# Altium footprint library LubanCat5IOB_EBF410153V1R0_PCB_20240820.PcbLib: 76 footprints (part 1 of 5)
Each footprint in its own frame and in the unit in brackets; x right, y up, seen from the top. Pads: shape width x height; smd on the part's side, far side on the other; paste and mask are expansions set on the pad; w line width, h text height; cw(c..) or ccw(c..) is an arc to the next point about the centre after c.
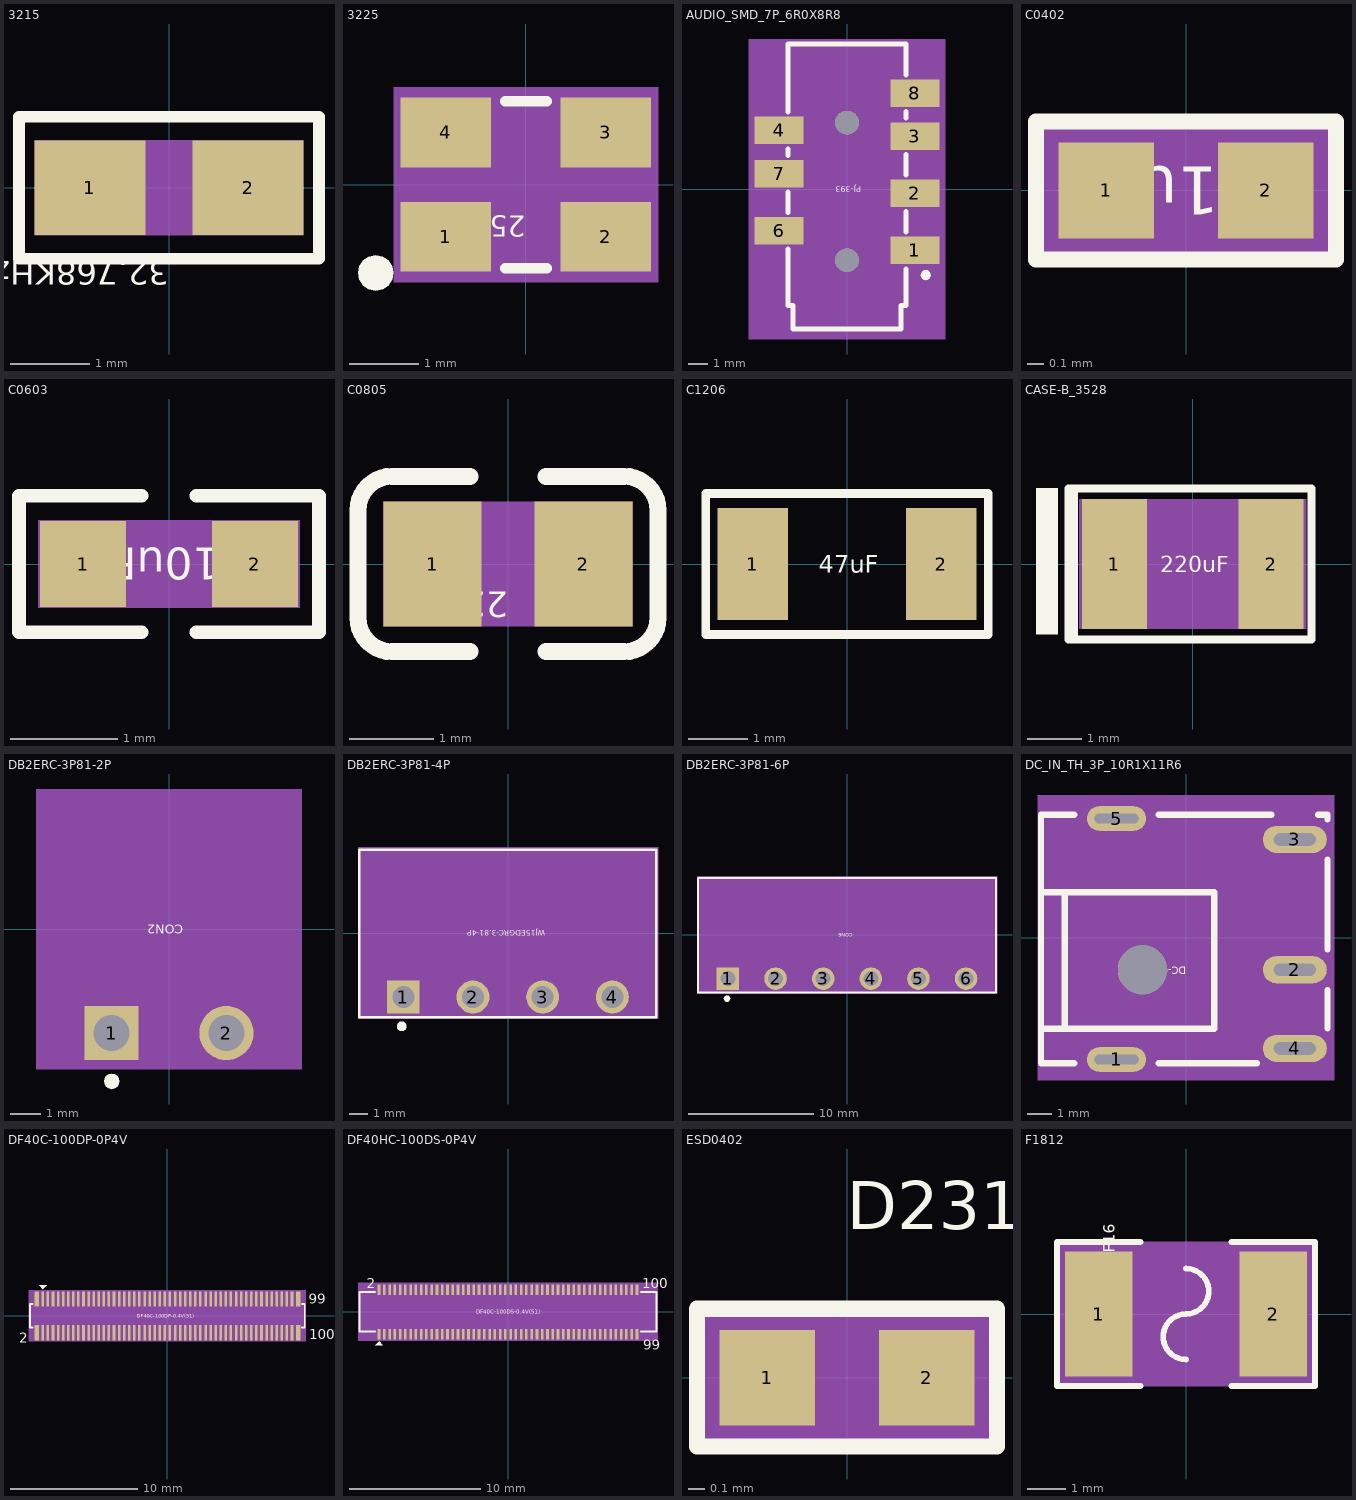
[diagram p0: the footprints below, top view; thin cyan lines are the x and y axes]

## 3215 [mm] "3215"
pads (2):
  rect 1.4x1.2 smd: 1(-1.001,0) 2(1.001,0)
Top Overlay:
  lines w0.15: -1.9,-0.899 1.9,-0.899 1.9,0.899 -1.9,0.899 -1.9,-0.899
  text "32.768KHz" at 0,-0.93 h0.3
Top 3D Body:
  region: -1.699,-0.599 1.699,-0.599 1.699,0.599 -1.699,0.599
Mechanical 15:
  text "1" at -1.001,-0.152 h0.38
  text "2" at 1.001,-0.152 h0.38
3D body: height 3.81, standoff 0, extent -1.699,-0.599 1.699,0.599

## 3225 [mm] "3225"
pads (4):
  rect 1.3x1 smd: 1(-1.15,-0.75) 2(1.15,-0.75) 3(1.15,0.75) 4(-1.15,0.75)
Top Overlay:
  dashed: -2.159,-1.015 -2.257,-1.035 -2.339,-1.09 -2.394,-1.172 -2.414,-1.27 -2.394,-1.368 -2.376,-1.395 -2.339,-1.45 -2.257,-1.505 -2.159,-1.525 -2.061,-1.505 -1.979,-1.45 -1.942,-1.395 -1.924,-1.368 -1.904,-1.27 -1.924,-1.172 -1.979,-1.09 -2.061,-1.035
  lines w0.15: -0.3,-1.2 0.3,-1.2 ; -0.3,1.2 0.3,1.2
  text "25MHz" at 0,-0.45 h0.3
Top 3D Body:
  region: -1.9,1.4 -1.9,-1.4 1.9,-1.4 1.9,1.4
Mechanical 15:
  text "3" at 1.15,0.394 h0.89
  text "2" at 1.15,-1.106 h0.89
  text "4" at -1.15,0.394 h0.89
  text "1" at -1.15,-1.106 h0.89
Top Assembly:
  lines w0.15: -1.6,-1.25 1.6,-1.25 1.6,1.25 -1.6,1.25 -1.6,-1.25
3D body: height 3.81, standoff 0, extent -1.9,-1.4 1.9,1.4

## AUDIO_SMD_7P_6R0X8R8 [mm] "AUDIO_SMD_7P_6R0X8R8"
pads (9):
  rect 2.5x1.4 smd: 1(3.45,-3.125) 2(3.45,-0.225) 3(3.45,2.675) 4(-3.45,2.975) 6(-3.45,-2.125) 7(-3.45,0.775) 8(3.45,4.875)
  round 1.2 hole 1.2 unplated: ""(0,-3.625) ""(0,3.375)
Top Overlay:
  dashed: 3.745,-4.375 3.765,-4.473 3.82,-4.555 3.902,-4.61 4,-4.63 4.098,-4.61 4.125,-4.592 4.18,-4.555 4.235,-4.473 4.255,-4.375 4.235,-4.277 4.18,-4.195 4.125,-4.158 4.098,-4.14 4,-4.12 3.902,-4.14 3.82,-4.195 3.765,-4.277
  lines w0.254: -3,-3.056 -3,-5.025 -3,-4.975 -3,-5.925 -2.75,-5.925 -2.75,-7.125 2.75,-7.125 2.75,-5.925 3,-5.925 3,-4.056 ; -3,-1.194 -3,-0.156 ; -3,1.706 -3,2.044 ; -3,3.906 -3,7.375 3,7.375 3,5.806 ; 3,-2.194 3,-1.156 ; 3,0.706 3,1.744 ; 3,3.606 3,3.944
  text "PJ-393" at 0.72,0.15 h0.3
Top 3D Body:
  region: -5,7.625 -5,-7.625 5,-7.625 5,7.625
Mechanical 15:
  text "6" at -3.196,-2.125 h0.64
  text "4" at -3.196,2.975 h0.64
  text "3" at 3.704,2.675 h0.64
  text "2" at 3.704,-0.225 h0.64
  text "1" at 3.704,-3.125 h0.64
  text "8" at 3.704,4.875 h0.64
  text "7" at -3.196,0.775 h0.64
3D body: height 3.81, standoff 0, extent -5,-7.625 5,7.625

## C0402 [mm] "C0402"
pads (2):
  rect 0.599x0.599 smd: 1(-0.5,0) 2(0.5,0)
Top Overlay:
  lines w0.102: -0.94,-0.432 0.94,-0.432 0.94,0.432 -0.94,0.432 -0.94,-0.432
  text "0.1uF" at 0.6,0.15 h0.3
Top 3D Body:
  region: 0.94,0.432 0.94,-0.432 -0.94,-0.432 -0.94,0.432
Mechanical 15:
  text "2" at 0.754,0 h0.64
  text "1" at -0.246,0 h0.64
Top Assembly:
  dashed: -0.94,-0.432 -0.94,0.432 0.94,0.432 0.94,-0.432
3D body: height 3.81, standoff 0, extent -0.94,-0.432 0.94,0.432

## C0603 [mil] "C0603"
pads (2):
  rect 31.5x31.5 smd: 1(-31.5,0) 2(31.5,0)
Top Overlay:
  lines w5: -10,-25 -55,-25 -55,25 -10,25 ; 10,-25 55,-25 55,25 10,25
  text "10uF" at 18.9,5.91 h11.81
Top 3D Body:
  region: -48,16 48,16 48,-16 -48,-16
Mechanical 15:
  text "1" at -13.5,0 h45
  text "2" at 49.5,0 h45
Top Assembly:
  text "C0603" at -117,37 h35
3D body: height 150, standoff 0, extent -48,-16 48,16

## C0805 [mm] "C0805"
pads (2):
  rect 1.16x1.47 smd: 1(-0.89,0) 2(0.89,0)
Top Overlay:
  lines w0.2: -0.45,-1.035 -1.37,-1.035 cw(c-1.37,-0.635) -1.77,-0.635 -1.77,0.635 cw(c-1.37,0.635) -1.37,1.035 -0.45,1.035 ; 0.45,-1.035 1.37,-1.035 ccw(c1.37,-0.635) 1.77,-0.635 1.77,0.635 ccw(c1.37,0.635) 1.37,1.035 0.45,1.035
  text "22uF" at 0,-0.33 h0.3
Top 3D Body:
  region: -1.47,-0.735 1.47,-0.735 1.47,0.735 -1.47,0.735
Mechanical 15:
  text "1" at -0.89,-0.315 h0.79
  text "2" at 0.89,-0.315 h0.79
3D body: height 3.81, standoff 0, extent -1.47,-0.735 1.47,0.735

## C1206 [mm] "C1206"
pads (2):
  rect 1.2x1.9 smd: 1(-1.6,0) 2(1.6,0)
Top Overlay:
  lines w0.15: -2.4,-1.2 -2.4,1.2 2.4,1.2 2.4,-1.2 0.6,-1.2 -2.4,-1.2
  text "47uF" at -0.48,-0.15 h0.3
Top 3D Body:
  lines w0.025: -2.4,-1.2 2.4,-1.2 2.4,1.2 -2.4,1.2 -2.4,-1.2
Mechanical 15:
  text "2" at 1.498,0 h0.25
  text "1" at -1.702,0 h0.25
Top Assembly:
  lines w0.025: -2.4,-1.2 2.4,-1.2 2.4,1.2 -2.4,1.2 -2.4,-1.2

## CASE-B_3528 [mm] "CASE-B_3528"
pads (2):
  rect 1.2x2.4 smd: 1(-1.45,0) 2(1.45,0)
Top Overlay:
  dashed: -2.9,1.4 -2.9,-1.3 -2.5,-1.3 -2.5,1.4
  lines w0.15: -2.2,1.4 -2.2,-1.4 2.2,-1.4 2.2,1.4 -2.3,1.4 -2.3,-1.4 -2.1,-1.4
  text "220uF" at -0.6,-0.15 h0.3
Top 3D Body:
  region: -2.1,1.2 -2.1,-1.2 2.1,-1.2 2.1,1.2
Mechanical 15:
  text "2" at 1.196,0 h0.64
  text "1" at -1.704,0 h0.64
Top Assembly:
  lines w0.15: -1.72,-1.1 1.78,-1.1 1.78,1.1 -1.72,1.1 -1.72,-1.1
3D body: height 3.81, standoff 0, extent -2.1,-1.2 2.1,1.2

## DB2ERC-3P81-2P [mm] "DB2ERC-3P81-2P"
pads (2):
  rect 1.8x1.8 / inner round 1.524 / far side rect 1.8x1.8 hole 1.2: 1(-1.905,-3.45)
  round 1.8 / inner round 1.524 / far side round 1.8 hole 1.2: 2(1.905,-3.45)
Top Overlay:
  dashed: -2.155,-5.05 -2.135,-5.148 -2.08,-5.23 -1.998,-5.285 -1.9,-5.305 -1.802,-5.285 -1.775,-5.267 -1.72,-5.23 -1.665,-5.148 -1.645,-5.05 -1.665,-4.952 -1.72,-4.87 -1.775,-4.833 -1.802,-4.815 -1.9,-4.795 -1.998,-4.815 -2.08,-4.87 -2.135,-4.952
  text "CON2" at 0.48,0.15 h0.3
Top 3D Body:
  region: -4.4,4.65 -4.4,-4.65 4.4,-4.65 4.4,4.65
Mechanical 15:
  text "2" at 2.159,-3.45 h0.64
  text "1" at -1.651,-3.45 h0.64
3D body: height 3.81, standoff 0, extent -4.4,-4.65 4.4,4.65

## DB2ERC-3P81-4P [mm] "DB2ERC-3P81-4P"
pads (4):
  rect 1.8x1.8 / inner round 1.524 / far side rect 1.8x1.8 hole 1.2: 1(-5.725,-3.5)
  round 1.8 / inner round 1.524 / far side round 1.8 hole 1.2: 2(-1.915,-3.5) 3(1.895,-3.5) 4(5.705,-3.5)
Top Overlay:
  dashed: -6.065,-5.1 -6.046,-5.198 -5.99,-5.28 -5.908,-5.335 -5.81,-5.355 -5.712,-5.335 -5.685,-5.317 -5.63,-5.28 -5.574,-5.198 -5.555,-5.1 -5.574,-5.002 -5.63,-4.92 -5.685,-4.883 -5.712,-4.864 -5.81,-4.845 -5.908,-4.864 -5.99,-4.92 -6.046,-5.002
  lines w0.15: -8.13,-4.6 8.11,-4.6 8.11,4.55 -8.13,4.55 -8.13,-4.6
  text "WJ15EDGRC-3.81-4P" at 2.04,0.15 h0.3
Top 3D Body:
  region: -8.2,4.7 -8.2,-4.7 8.2,-4.7 8.2,4.7
Mechanical 15:
  text "4" at 5.959,-3.5 h0.64
  text "3" at 2.149,-3.5 h0.64
  text "1" at -5.471,-3.5 h0.64
  text "2" at -1.661,-3.5 h0.64
3D body: height 3.81, standoff 0, extent -8.2,-4.7 8.2,4.7

## DB2ERC-3P81-6P [mm] "DB2ERC-3P81-6P"
pads (6):
  rect 1.8x1.8 / inner round 1.524 / far side rect 1.8x1.8 hole 1.2: 1(-9.525,-3.5)
  round 1.8 hole 1.2: 2(-5.715,-3.5) 5(5.715,-3.5)
  round 1.8 / inner round 1.524 / far side round 1.8 hole 1.2: 3(-1.905,-3.5) 4(1.905,-3.5) 6(9.525,-3.5)
Top Overlay:
  dashed: -9.855,-5.1 -9.836,-5.198 -9.78,-5.28 -9.698,-5.335 -9.6,-5.355 -9.502,-5.335 -9.475,-5.317 -9.42,-5.28 -9.364,-5.198 -9.345,-5.1 -9.364,-5.002 -9.42,-4.92 -9.475,-4.883 -9.502,-4.864 -9.6,-4.845 -9.698,-4.864 -9.78,-4.92 -9.836,-5.002
  lines w0.15: -11.93,-4.6 11.93,-4.6 11.93,4.55 -11.93,4.55 -11.93,-4.6
  text "CON6" at 0.48,0.15 h0.3
Top 3D Body:
  region: -12,4.7 -12,-4.7 12,-4.7 12,4.7
Mechanical 15:
  text "5" at 5.969,-3.5 h0.64
  text "2" at -5.461,-3.5 h0.64
  text "6" at 9.779,-3.5 h0.64
  text "4" at 2.159,-3.5 h0.64
  text "1" at -9.271,-3.5 h0.64
  text "3" at -1.651,-3.5 h0.64
3D body: height 3.81, standoff 0, extent -12,-4.7 12,4.7

## DC_IN_TH_3P_10R1X11R6 [mil] "DC_IN_TH_3P_10R1X11R6"
pads (6):
  oval 94.5x39.4 / inner round 60 / far side oval 94.5x39.4 hole 70.9 slot 15.7 at 90 deg: 1(-111.25,-194.9) 5(-111.25,190.9)
  oval 102.4x43.3 hole 66.9 slot 19.7 at 90 deg: 2(174.25,-51.2) 3(174.25,157.4)
  oval 102.4x43.3 / inner round 60 / far side oval 102.4x43.3 hole 66.9 slot 19.7 at 90 deg: 4(174.25,-177.2)
  round 78.7 hole 78.7 unplated: ""(-69.85,-51.2)
Top Overlay:
  lines w10: -232.25,-145.7 45.25,-145.7 45.25,72.8 -222.45,72.8 -232.25,72.8 ; -193.95,-145.7 -193.95,72.8 ; -178.95,-200.8 -232.25,-200.8 -232.25,196.8 -178.95,196.8 ; -43.45,-200.8 113.65,-200.8 ; -43.45,196.8 136.95,196.8 ; 211.45,196.8 226.35,196.8 226.35,189.7 ; 226.35,-145 226.35,-83.5 ; 226.35,-19 226.35,125.2
  text "DC-044A-20A" at 0.01,-46.06 h11.81
Top 3D Body:
  region: -237.25,-228.4 237.25,-228.4 237.25,228.4 -237.25,228.4
Mechanical 15:
  text "4" at 174.25,-187.2 h25
  text "2" at 174.25,-61.2 h25
  text "3" at 174.25,147.4 h25
  text "5" at -111.25,180.9 h25
  text "1" at -111.25,-204.9 h25
Mechanical 23:
  dashed: -232.25,-141.8 41.35,-141.8 41.35,68.9 -232.25,68.9 -232.25,78.7 51.15,78.7 51.15,-151.6 -232.25,-151.6
3D body: height 150, standoff 0, extent -237.25,-228.4 237.25,228.4

## DF40C-100DP-0P4V [mm] "DF40C-100DP-0P4V"
pads (104):
  rect 0.2x1.2 smd: 1(-9.8,1.325) 2(-9.8,-1.325) 3(-9.4,1.325) 4(-9.4,-1.325) 5(-9,1.325) 6(-9,-1.325) 7(-8.6,1.325) 8(-8.6,-1.325) 9(-8.2,1.325) 10(-8.2,-1.325) 11(-7.8,1.325) 12(-7.8,-1.325) 13(-7.4,1.325) 14(-7.4,-1.325) 15(-7,1.325) 16(-7,-1.325) 17(-6.6,1.325) 18(-6.6,-1.325) 19(-6.2,1.325) 20(-6.2,-1.325) 21(-5.8,1.325) 22(-5.8,-1.325) 23(-5.4,1.325) 24(-5.4,-1.325) 25(-5,1.325) 26(-5,-1.325) 27(-4.6,1.325) 28(-4.6,-1.325) 29(-4.2,1.325) 30(-4.2,-1.325) 31(-3.8,1.325) 32(-3.8,-1.325) 33(-3.4,1.325) 34(-3.4,-1.325) 35(-3,1.325) 36(-3,-1.325) 37(-2.6,1.325) 38(-2.6,-1.325) 39(-2.2,1.325) 40(-2.2,-1.325) 41(-1.8,1.325) 42(-1.8,-1.325) 43(-1.4,1.325) 44(-1.4,-1.325) 45(-1,1.325) 46(-1,-1.325) 47(-0.6,1.325) 48(-0.6,-1.325) 49(-0.2,1.325) 50(-0.2,-1.325) 51(0.2,1.325) 52(0.2,-1.325) 53(0.6,1.325) 54(0.6,-1.325) 55(1,1.325) 56(1,-1.325) 57(1.4,1.325) 58(1.4,-1.325) 59(1.8,1.325) 60(1.8,-1.325) 61(2.2,1.325) 62(2.2,-1.325) 63(2.6,1.325) 64(2.6,-1.325) 65(3,1.325) 66(3,-1.325) 67(3.4,1.325) 68(3.4,-1.325) 69(3.8,1.325) 70(3.8,-1.325) 71(4.2,1.325) 72(4.2,-1.325) 73(4.6,1.325) 74(4.6,-1.325) 75(5,1.325) 76(5,-1.325) 77(5.4,1.325) 78(5.4,-1.325) 79(5.8,1.325) 80(5.8,-1.325) 81(6.2,1.325) 82(6.2,-1.325) 83(6.6,1.325) 84(6.6,-1.325) 85(7,1.325) 86(7,-1.325) 87(7.4,1.325) 88(7.4,-1.325) 89(7.8,1.325) 90(7.8,-1.325) 91(8.2,1.325) 92(8.2,-1.325) 93(8.6,1.325) 94(8.6,-1.325) 95(9,1.325) 96(9,-1.325) 97(9.4,1.325) 98(9.4,-1.325) 99(9.8,1.325) 100(9.8,-1.325)
  rect 0.35x1.2 smd: 101(-10.275,1.325) 102(-10.275,-1.325) 103(10.275,1.325) 104(10.275,-1.325)
Top Overlay:
  dashed: -10.1,2.4 -9.5,2.4 -9.8,2.1
  lines w0.15: -10.6,-0.925 -10.8,-0.925 -10.8,0.925 -10.6,0.925 ; 10.6,-0.925 10.8,-0.925 10.8,0.925 10.6,0.925
  text "DF40C-100DP-0.4V(51)" at -2.4,-0.15 h0.3
  text "99" at 11.111,0.945 h0.76
  text "100" at 11.161,-1.849 h0.76
  text "2" at -11.673,-2.103 h0.76
Top 3D Body:
  region: -10.9,2 -10.9,-2 10.9,-2 10.9,2
Mechanical 15:
  text "14" at -7.54,-1.325 h0.3
  text "16" at -7.14,-1.325 h0.3
  text "13" at -7.523,1.342 h0.3
  text "96" at 8.86,-1.325 h0.3
  text "40" at -2.34,-1.325 h0.3
  text "15" at -7.123,1.342 h0.3
  text "42" at -1.94,-1.325 h0.3
  text "19" at -6.323,1.342 h0.3
  text "54" at 0.46,-1.325 h0.3
  text "24" at -5.54,-1.325 h0.3
  text "56" at 0.86,-1.325 h0.3
  text "26" at -5.14,-1.325 h0.3
  text "74" at 4.46,-1.325 h0.3
  text "5" at -9.003,1.342 h0.3
  text "79" at 5.677,1.342 h0.3
  text "91" at 8.078,1.342 h0.3
  text "1" at -9.803,1.342 h0.3
  text "2" at -9.82,-1.325 h0.3
  text "104" at 10.015,-1.325 h0.3
  text "82" at 6.06,-1.325 h0.3
  text "103" at 10.015,1.325 h0.3
  text "57" at 1.277,1.342 h0.3
  text "73" at 4.477,1.342 h0.3
  text "58" at 1.26,-1.325 h0.3
  text "76" at 4.86,-1.325 h0.3
  text "52" at 0.06,-1.325 h0.3
  text "34" at -3.54,-1.325 h0.3
  text "18" at -6.74,-1.325 h0.3
  text "12" at -7.94,-1.325 h0.3
  text "11" at -7.923,1.342 h0.3
  text "17" at -6.723,1.342 h0.3
  text "27" at -4.722,1.342 h0.3
  text "33" at -3.522,1.342 h0.3
  text "51" at 0.078,1.342 h0.3
  text "28" at -4.74,-1.325 h0.3
  text "101" at -10.535,1.325 h0.3
  text "102" at -10.535,-1.325 h0.3
  text "44" at -1.54,-1.325 h0.3
  text "100" at 9.54,-1.325 h0.3
  text "86" at 6.86,-1.325 h0.3
  text "30" at -4.34,-1.325 h0.3
  text "64" at 2.46,-1.325 h0.3
  text "25" at -5.122,1.342 h0.3
  text "98" at 9.26,-1.325 h0.3
  text "94" at 8.46,-1.325 h0.3
  text "62" at 2.06,-1.325 h0.3
  text "29" at -4.322,1.342 h0.3
  text "66" at 2.86,-1.325 h0.3
  text "32" at -3.94,-1.325 h0.3
  text "60" at 1.66,-1.325 h0.3
  text "48" at -0.74,-1.325 h0.3
  text "84" at 6.46,-1.325 h0.3
  text "50" at -0.34,-1.325 h0.3
  text "93" at 8.478,1.342 h0.3
  text "97" at 9.278,1.342 h0.3
  text "95" at 8.878,1.342 h0.3
  text "99" at 9.678,1.342 h0.3
  text "88" at 7.26,-1.325 h0.3
  text "70" at 3.66,-1.325 h0.3
  text "92" at 8.06,-1.325 h0.3
  text "61" at 2.077,1.342 h0.3
  text "3" at -9.403,1.342 h0.3
  text "55" at 0.877,1.342 h0.3
  text "59" at 1.677,1.342 h0.3
  text "67" at 3.277,1.342 h0.3
  text "69" at 3.677,1.342 h0.3
  text "6" at -9.02,-1.325 h0.3
  text "4" at -9.42,-1.325 h0.3
  text "10" at -8.34,-1.325 h0.3
  text "8" at -8.62,-1.325 h0.3
  text "21" at -5.922,1.342 h0.3
  text "41" at -1.922,1.342 h0.3
  text "39" at -2.322,1.342 h0.3
  text "37" at -2.722,1.342 h0.3
  text "80" at 5.66,-1.325 h0.3
  text "35" at -3.122,1.342 h0.3
  text "71" at 4.077,1.342 h0.3
  text "83" at 6.478,1.342 h0.3
  text "77" at 5.277,1.342 h0.3
  text "65" at 2.877,1.342 h0.3
  text "49" at -0.322,1.342 h0.3
  text "9" at -8.203,1.342 h0.3
  text "63" at 2.477,1.342 h0.3
  text "47" at -0.722,1.342 h0.3
  text "23" at -5.522,1.342 h0.3
  text "89" at 7.678,1.342 h0.3
  text "31" at -3.922,1.342 h0.3
  text "90" at 7.66,-1.325 h0.3
  text "87" at 7.278,1.342 h0.3
  text "85" at 6.878,1.342 h0.3
  text "75" at 4.877,1.342 h0.3
  text "81" at 6.077,1.342 h0.3
  text "78" at 5.26,-1.325 h0.3
  text "68" at 3.26,-1.325 h0.3
  text "45" at -1.122,1.342 h0.3
  text "43" at -1.522,1.342 h0.3
  text "46" at -1.14,-1.325 h0.3
  text "7" at -8.603,1.342 h0.3
  text "36" at -3.14,-1.325 h0.3
  text "38" at -2.74,-1.325 h0.3
  text "72" at 4.06,-1.325 h0.3
  text "20" at -6.34,-1.325 h0.3
  text "22" at -5.94,-1.325 h0.3
  text "53" at 0.477,1.342 h0.3
Top Assembly:
  lines w0.15: -10.8,-1.5 -10.8,1.5 0,1.5 10.8,1.5 10.8,-1.5 -10.8,-1.5
3D body: height 3.81, standoff 0, extent -10.9,-2 10.9,2

## DF40HC-100DS-0P4V [mm] "DF40HC-100DS-0P4V"
pads (100):
  rect 0.2x0.8 smd: 1(-9.8,-1.7) 2(-9.8,1.7) 3(-9.4,-1.7) 4(-9.4,1.7) 5(-9,-1.7) 6(-9,1.7) 7(-8.6,-1.7) 8(-8.6,1.7) 9(-8.2,-1.7) 10(-8.2,1.7) 11(-7.8,-1.7) 12(-7.8,1.7) 13(-7.4,-1.7) 14(-7.4,1.7) 15(-7,-1.7) 16(-7,1.7) 17(-6.6,-1.7) 18(-6.6,1.7) 19(-6.2,-1.7) 20(-6.2,1.7) 21(-5.8,-1.7) 22(-5.8,1.7) 23(-5.4,-1.7) 24(-5.4,1.7) 25(-5,-1.7) 26(-5,1.7) 27(-4.6,-1.7) 28(-4.6,1.7) 29(-4.2,-1.7) 30(-4.2,1.7) 31(-3.8,-1.7) 32(-3.8,1.7) 33(-3.4,-1.7) 34(-3.4,1.7) 35(-3,-1.7) 36(-3,1.7) 37(-2.6,-1.7) 38(-2.6,1.7) 39(-2.2,-1.7) 40(-2.2,1.7) 41(-1.8,-1.7) 42(-1.8,1.7) 43(-1.4,-1.7) 44(-1.4,1.7) 45(-1,-1.7) 46(-1,1.7) 47(-0.6,-1.7) 48(-0.6,1.7) 49(-0.2,-1.7) 50(-0.2,1.7) 51(0.2,-1.7) 52(0.2,1.7) 53(0.6,-1.7) 54(0.6,1.7) 55(1,-1.7) 56(1,1.7) 57(1.4,-1.7) 58(1.4,1.7) 59(1.8,-1.7) 60(1.8,1.7) 61(2.2,-1.7) 62(2.2,1.7) 63(2.6,-1.7) 64(2.6,1.7) 65(3,-1.7) 66(3,1.7) 67(3.4,-1.7) 68(3.4,1.7) 69(3.8,-1.7) 70(3.8,1.7) 71(4.2,-1.7) 72(4.2,1.7) 73(4.6,-1.7) 74(4.6,1.7) 75(5,-1.7) 76(5,1.7) 77(5.4,-1.7) 78(5.4,1.7) 79(5.8,-1.7) 80(5.8,1.7) 81(6.2,-1.7) 82(6.2,1.7) 83(6.6,-1.7) 84(6.6,1.7) 85(7,-1.7) 86(7,1.7) 87(7.4,-1.7) 88(7.4,1.7) 89(7.8,-1.7) 90(7.8,1.7) 91(8.2,-1.7) 92(8.2,1.7) 93(8.6,-1.7) 94(8.6,1.7) 95(9,-1.7) 96(9,1.7) 97(9.4,-1.7) 98(9.4,1.7) 99(9.8,-1.7) 100(9.8,1.7)
Top Overlay:
  dashed: -10.1,-2.55 -9.5,-2.55 -9.8,-2.25
  lines w0.15: -10.1,-1.5 -11.3,-1.5 -11.3,1.5 -10.1,1.5 ; 10.1,-1.5 11.3,-1.5 11.3,1.5 10.1,1.5
  text "DF40C-100DS-0.4V(51)" at -2.4,-0.15 h0.3
  text "2" at -10.744,1.808 h0.76
  text "100" at 10.186,1.808 h0.76
  text "99" at 10.262,-2.891 h0.76
Top 3D Body:
  region: -11.4,2.2 -11.4,-2.2 11.4,-2.2 11.4,2.2
Mechanical 15:
  text "34" at -3.522,1.717 h0.3
  text "36" at -3.122,1.717 h0.3
  text "68" at 3.277,1.717 h0.3
  text "64" at 2.477,1.717 h0.3
  text "31" at -3.922,-1.682 h0.3
  text "6" at -9.003,1.717 h0.3
  text "4" at -9.403,1.717 h0.3
  text "8" at -8.603,1.717 h0.3
  text "30" at -4.322,1.717 h0.3
  text "28" at -4.722,1.717 h0.3
  text "91" at 8.078,-1.682 h0.3
  text "82" at 6.077,1.717 h0.3
  text "62" at 2.077,1.717 h0.3
  text "75" at 4.877,-1.682 h0.3
  text "53" at 0.477,-1.682 h0.3
  text "43" at -1.522,-1.682 h0.3
  text "37" at -2.722,-1.682 h0.3
  text "99" at 9.678,-1.682 h0.3
  text "27" at -4.722,-1.682 h0.3
  text "18" at -6.723,1.717 h0.3
  text "10" at -8.323,1.717 h0.3
  text "26" at -5.122,1.717 h0.3
  text "38" at -2.722,1.717 h0.3
  text "32" at -3.922,1.717 h0.3
  text "54" at 0.477,1.717 h0.3
  text "88" at 7.278,1.717 h0.3
  text "2" at -9.803,1.717 h0.3
  text "1" at -9.803,-1.682 h0.3
  text "11" at -7.923,-1.682 h0.3
  text "17" at -6.723,-1.682 h0.3
  text "72" at 4.077,1.717 h0.3
  text "94" at 8.478,1.717 h0.3
  text "100" at 9.558,1.717 h0.3
  text "97" at 9.278,-1.682 h0.3
  text "50" at -0.322,1.717 h0.3
  text "35" at -3.122,-1.682 h0.3
  text "77" at 5.277,-1.682 h0.3
  text "76" at 4.877,1.717 h0.3
  text "67" at 3.277,-1.682 h0.3
  text "78" at 5.277,1.717 h0.3
  text "84" at 6.478,1.717 h0.3
  text "86" at 6.878,1.717 h0.3
  text "23" at -5.522,-1.682 h0.3
  text "57" at 1.277,-1.682 h0.3
  text "25" at -5.122,-1.682 h0.3
  text "61" at 2.077,-1.682 h0.3
  text "93" at 8.478,-1.682 h0.3
  text "9" at -8.203,-1.682 h0.3
  text "47" at -0.722,-1.682 h0.3
  text "15" at -7.123,-1.682 h0.3
  text "55" at 0.877,-1.682 h0.3
  text "5" at -9.003,-1.682 h0.3
  text "51" at 0.078,-1.682 h0.3
  text "85" at 6.878,-1.682 h0.3
  text "63" at 2.477,-1.682 h0.3
  text "41" at -1.922,-1.682 h0.3
  text "81" at 6.077,-1.682 h0.3
  text "33" at -3.522,-1.682 h0.3
  text "73" at 4.477,-1.682 h0.3
  text "83" at 6.478,-1.682 h0.3
  text "52" at 0.078,1.717 h0.3
  text "16" at -7.123,1.717 h0.3
  text "12" at -7.923,1.717 h0.3
  text "14" at -7.523,1.717 h0.3
  text "48" at -0.722,1.717 h0.3
  text "3" at -9.403,-1.682 h0.3
  text "19" at -6.323,-1.682 h0.3
  text "89" at 7.678,-1.682 h0.3
  text "56" at 0.877,1.717 h0.3
  text "79" at 5.677,-1.682 h0.3
  text "40" at -2.322,1.717 h0.3
  text "24" at -5.522,1.717 h0.3
  text "42" at -1.922,1.717 h0.3
  text "44" at -1.522,1.717 h0.3
  text "29" at -4.322,-1.682 h0.3
  text "66" at 2.877,1.717 h0.3
  text "92" at 8.078,1.717 h0.3
  text "58" at 1.277,1.717 h0.3
  text "21" at -5.922,-1.682 h0.3
  text "90" at 7.678,1.717 h0.3
  text "80" at 5.677,1.717 h0.3
  text "13" at -7.523,-1.682 h0.3
  text "39" at -2.322,-1.682 h0.3
  text "60" at 1.677,1.717 h0.3
  text "45" at -1.122,-1.682 h0.3
  text "74" at 4.477,1.717 h0.3
  text "71" at 4.077,-1.682 h0.3
  text "69" at 3.677,-1.682 h0.3
  text "96" at 8.878,1.717 h0.3
  text "65" at 2.877,-1.682 h0.3
  text "46" at -1.122,1.717 h0.3
  text "59" at 1.677,-1.682 h0.3
  text "98" at 9.278,1.717 h0.3
  text "7" at -8.603,-1.682 h0.3
  text "87" at 7.278,-1.682 h0.3
  text "95" at 8.878,-1.682 h0.3
  text "20" at -6.323,1.717 h0.3
  text "22" at -5.922,1.717 h0.3
  text "70" at 3.677,1.717 h0.3
  text "49" at -0.322,-1.682 h0.3
Top Assembly:
  lines w0.15: -11.3,-1.7 11.3,-1.7 11.3,1.7 0,1.7 -11.3,1.7 -11.3,-1.7
3D body: height 3.81, standoff 0, extent -11.4,-2.2 11.4,2.2

## ESD0402 [mm] "ESD0402"
pads (2):
  rect 0.599x0.599 smd: 1(-0.5,0) 2(0.5,0)
Top Overlay:
  lines w0.102: -0.94,-0.432 -0.94,0.432 0.94,0.432 0.94,-0.432 -0.94,-0.432
  text "D2315-3R3" at 0,0.93 h0.3
Top 3D Body:
  region: 0.94,0.432 0.94,-0.432 -0.94,-0.432 -0.94,0.432
Mechanical 15:
  text "1" at -0.5,0.254 h0.64
  text "2" at 0.5,0.254 h0.64
Top Assembly:
  dashed: -0.94,-0.432 -0.94,0.432 0.94,0.432 0.94,-0.432
3D body: height 3.81, standoff 0, extent -0.94,-0.432 0.94,0.432

## F1812 [mm] "F1812"
pads (2):
  rect 1.78x3.3 smd: 1(-2.305,0) 2(2.305,0)
Top Overlay:
  lines w0.15: -1.2,-1.9 -3.4,-1.9 -3.4,1.9 -1.2,1.9 ; 0,-1.2 cw(c0,-0.6) 0,0 ccw(c0,0.6) 0,1.2 ; 1.2,-1.9 3.4,-1.9 3.4,1.9 1.2,1.9
  text "SMD1812P200TF16" at -1.882,-1.673 h0.3
Top 3D Body:
  region: -3.4,-1.9 3.4,-1.9 3.4,1.9 -3.4,1.9
Mechanical 15:
  text "1" at -2.305,-0.122 h0.3
  text "2" at 2.305,-0.122 h0.3
3D body: height 3.81, standoff 0, extent -3.4,-1.9 3.4,1.9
